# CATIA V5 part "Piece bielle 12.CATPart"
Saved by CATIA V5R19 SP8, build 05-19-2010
Part number: Piece bielle 12
Bounding box of the stored display mesh (mm): x -5.898 to 35.997, y 31.132 to 92.914, z 6.009 to 11.991
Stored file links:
  G:\EU_thinkMotion\CFAO_2010\MMS_groupe3\MMS_groupe3\A reprendre\lpastor\lpastor\Piece bielle 12.CATPart
  C:\Users\Loïc\Documents\IFMA\Cours 2A\CFAO\Thinkmotion\Fourche avant.CATProduct
  G:\EU_thinkMotion\CFAO_2010\MMS_groupe3\MMS_groupe3\A reprendre\lpastor\lpastor\Pieces.CATProduct
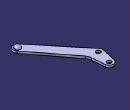
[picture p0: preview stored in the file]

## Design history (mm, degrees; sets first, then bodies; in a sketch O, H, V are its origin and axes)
External parameters (linked from other documents)
  External.Parametre_diametre_interieur_rotule_haute = 0.003
  External.Parametre_rayon_interieur_rotule_haute = 0.003
Set1
  Plane1: linked copy from another document
  Line1 "Droite D (bielle 12)": linked copy from another document
  Line2 "Droite C (bielle 12)": linked copy from another document
  Line3 "Droite E (bielle 12)": linked copy from another document
  Plane2: linked copy from another document
  Plane3: linked copy from another document
  Line4 "Droite CE (bielle 12)": linked copy from another document
  Line5 "Droite CD (bielle 12)": linked copy from another document
  Plane4: linked copy from another document
Body1 (main body)
  Sketch1 on Plane3, origin (0, 0, 9), H (1, 0, 0), V (0, 1, 0)
    arc A1 centre (32, 35) radius 3 from (30.9903, 32.175) to (33.0097, 37.825) ccw
    point P1 (32, 35)
    reference projected point E1 (32, 35) from Line3
    line L1 (33.0097, 37.825) -> (32, 35)
    line L2 (32, 35) -> (30.9903, 32.175)
    point P3 (30.9903, 32.175)
    radius A1 = 3 {= External.Parametre_rayon_interieur_rotule_haute}
    coincidence: P1 E1, P3 L1
  Shaft1: profile Sketch1, axis Sketch1.L1, angle 360
  Sketch2 on Plane4, origin (0, 0, 8), H (1, 0, 0), V (0, 1, 0)
    point P1 (-2.8976, 89.8994)
    line L1 (-2.8976, 89.8994) -> (-5.8976, 76.8994)
    arc A1 centre (-2, 76) radius 4 from (-5.8976, 76.8994) to (-5.079, 73.4467) ccw
    point P3 (-2, 76)
    line L2 (-5.079, 73.4467) -> (28.921, 32.4467)
    arc A2 centre (32, 35) radius 4 from (28.921, 32.4467) to (35.1663, 37.4443) ccw
    point P6 (32, 35)
    line L3 (35.1663, 37.4443) -> (7.5237, 73.2511)
    arc A3 centre (13.8563, 78.1398) radius 8 from (7.5237, 73.2511) to (5.8791, 77.536) cw
    line L4 (5.8791, 77.536) -> (4.9886, 89.3019)
    arc A4 centre (1, 89) radius 4 from (4.9886, 89.3019) to (-2.8976, 89.8994) ccw
    point P12 (1, 89)
    point P13 (-2.8976, 89.8994)
    line L5 (-2.8976, 89.8994) -> (-2.8976, 89.8994)
    reference projected point E1 (32, 35) from Line3
    reference projected point E2 (-2, 76) from Line2
    reference projected point E3 (1, 89) from Line1
    circle A5 centre (1, 89) radius 2
    point P14 (1, 89)
    circle A6 centre (-2, 76) radius 2
    point P15 (-2, 76)
    reference projected point E4 (-2, 76) from Line2
    reference projected point E5 (1, 89) from Line1
    radius A2 = 4
    radius A1 = 4
    radius A4 = 4
    radius A3 = 8
    distance A1 A3 = 12
    angle L3 L2 = 178
    radius A6 = 2
    radius A5 = 2
    tangency: A1 L1, L2 A1, A2 L2, A3 L3, L4 A3, A4 L1, A4 L4, A2 L3
    coincidence: P13 P1, E1 P6, P3 E2, P12 E3, P15 E4, P14 E5
  Pad1: profile Sketch2, direction (0, 0, 1), up to Plane2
